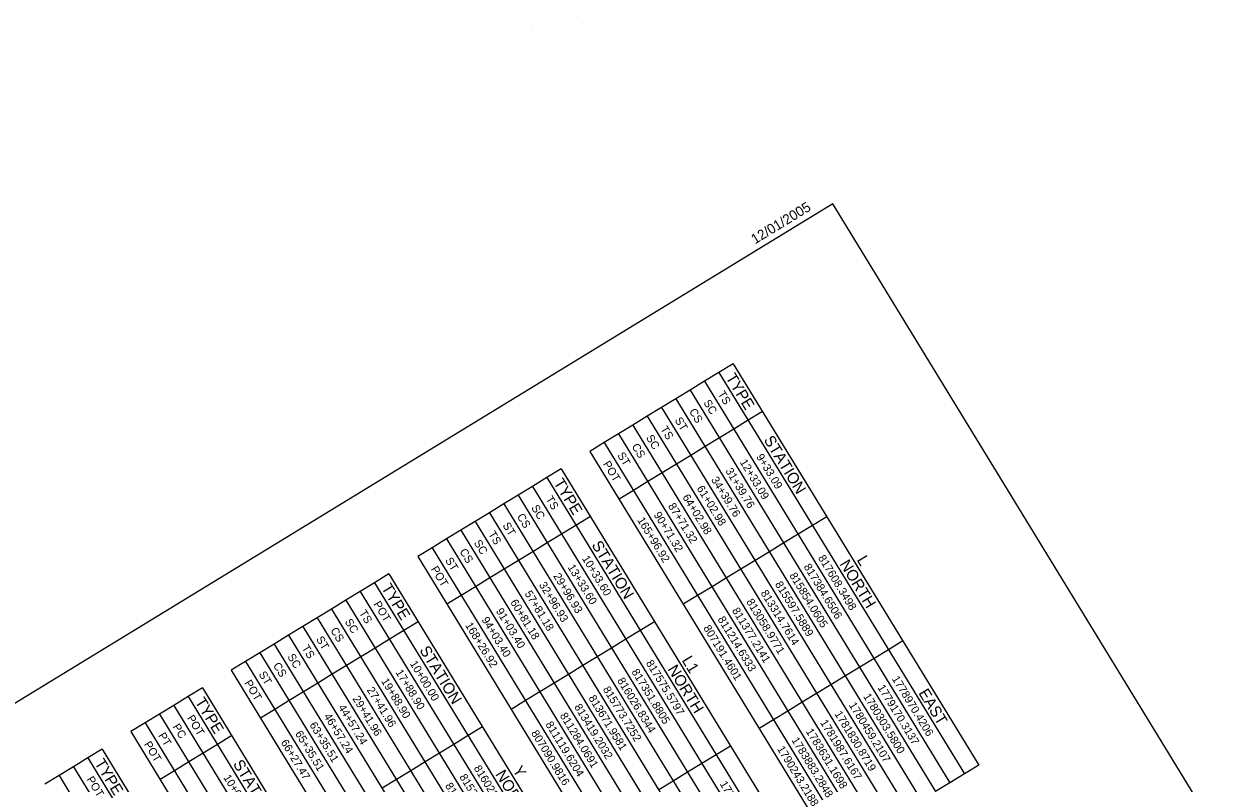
# Model space of a CAD drawing. Extents: x 1753086 to 1770987, y 792577 to 812636.
# Drawn here: x 1758064 to 1764623, y 808460 to 812636 of the extents above; entities that cross this region are included whole.
import ezdxf

# ---------------------------------------------------------------- set-up
doc = ezdxf.new("R2010")
doc.units = 0
for name, color, linetype in [('CTL Sheet Border CELL', 7, 'Continuous'), ('CTL Sheet Notes CELL', 7, 'Continuous'), ('CTL Sheet Table Cell', 7, 'Continuous'), ('CTL Sheet Text', 7, 'Continuous'), ('Sheet Data Field CELL', 7, 'Continuous')]:
    doc.layers.add(name, color=color, linetype=linetype)

msp = doc.modelspace()

# ---------------------------------------------------------------- linework, layer by layer
at = {"layer": 'CTL Sheet Border CELL'}
msp.add_lwpolyline([(1770671.7, 798289.4), (1762511, 811645.8), (1753161.6, 805933.4), (1761322.3, 792577)], close=True, dxfattribs=at)
at = {"layer": 'CTL Sheet Table Cell'}
for p, q in [((1761963.3, 810766.2), (1761884.4, 810718)), ((1761963.3, 810766.2), (1763312.2, 808558.5)), ((1761884.4, 810718), (1761805.6, 810669.9)), ((1761884.4, 810718), (1763233.3, 808510.3)), ((1761726.7, 810621.7), (1761647.9, 810573.5)), ((1761805.6, 810669.9), (1761726.7, 810621.7)), ((1761726.7, 810621.7), (1763075.6, 808414)), ((1761805.6, 810669.9), (1763154.5, 808462.2)), ((1761647.9, 810573.5), (1761569, 810525.3)), ((1761647.9, 810573.5), (1762996.8, 808365.8)), ((1761490.2, 810477.2), (1761411.3, 810429)), ((1761569, 810525.3), (1761490.2, 810477.2)), ((1761490.2, 810477.2), (1762839.1, 808269.4)), ((1761569, 810525.3), (1762917.9, 808317.6)), ((1762123.8, 810503.4), (1762045, 810455.2)), ((1761411.3, 810429), (1761332.5, 810380.8)), ((1761411.3, 810429), (1762760.2, 808221.3)), ((1762045, 810455.2), (1761966.1, 810407)), ((1761332.5, 810380.8), (1761253.6, 810332.6)), ((1761332.5, 810380.8), (1762681.4, 808173.1)), ((1761887.3, 810358.9), (1761808.5, 810310.7)), ((1761966.1, 810407), (1761887.3, 810358.9)), ((1761253.6, 810332.6), (1761174.8, 810284.5)), ((1761174.8, 810284.5), (1762523.7, 808076.7)), ((1761253.6, 810332.6), (1762602.5, 808124.9)), ((1761808.5, 810310.7), (1761729.6, 810262.5)), ((1761650.8, 810214.3), (1761571.9, 810166.2)), ((1761729.6, 810262.5), (1761650.8, 810214.3)), ((1761017.1, 810188.1), (1760938.2, 810139.9)), ((1761017.1, 810188.1), (1762366, 807980.4)), ((1761571.9, 810166.2), (1761493.1, 810118)), ((1760859.4, 810091.8), (1760780.5, 810043.6)), ((1760938.2, 810139.9), (1760859.4, 810091.8)), ((1760859.4, 810091.8), (1762208.3, 807884)), ((1760938.2, 810139.9), (1762287.2, 807932.2)), ((1761493.1, 810118), (1761414.2, 810069.8)), ((1760780.5, 810043.6), (1760701.7, 809995.4)), ((1760780.5, 810043.6), (1762129.5, 807835.9)), ((1761414.2, 810069.8), (1761335.4, 810021.6)), ((1760701.7, 809995.4), (1760622.9, 809947.2)), ((1760701.7, 809995.4), (1762050.6, 807787.7)), ((1760544, 809899.1), (1760465.2, 809850.9)), ((1760622.9, 809947.2), (1760544, 809899.1)), ((1760544, 809899.1), (1761892.9, 807691.3)), ((1760622.9, 809947.2), (1761971.8, 807739.5)), ((1761177.7, 809925.3), (1761098.8, 809877.1)), ((1762477.1, 809925.2), (1762398.3, 809877)), ((1760465.2, 809850.9), (1760386.3, 809802.7)), ((1760465.2, 809850.9), (1761814.1, 807643.2)), ((1761020, 809828.9), (1760941.1, 809780.8)), ((1761098.8, 809877.1), (1761020, 809828.9)), ((1762319.4, 809828.8), (1762240.6, 809780.7)), ((1762398.3, 809877), (1762319.4, 809828.8)), ((1760307.5, 809754.5), (1760228.6, 809706.4)), ((1760386.3, 809802.7), (1760307.5, 809754.5)), ((1760307.5, 809754.5), (1761656.4, 807546.8)), ((1760386.3, 809802.7), (1761735.2, 807595)), ((1760941.1, 809780.8), (1760862.3, 809732.6)), ((1762240.6, 809780.7), (1762161.7, 809732.5)), ((1760228.6, 809706.4), (1761577.5, 807498.6)), ((1760862.3, 809732.6), (1760783.4, 809684.4)), ((1762161.7, 809732.5), (1762082.9, 809684.3)), ((1760704.6, 809636.2), (1760625.7, 809588.1)), ((1760783.4, 809684.4), (1760704.6, 809636.2)), ((1762004, 809636.1), (1761925.2, 809588)), ((1762082.9, 809684.3), (1762004, 809636.1)), ((1759992.1, 809561.8), (1759913.2, 809513.7)), ((1760070.9, 809610), (1759992.1, 809561.8)), ((1759992.1, 809561.8), (1761341, 807354.1)), ((1760070.9, 809610), (1761419.8, 807402.3)), ((1760625.7, 809588.1), (1760546.9, 809539.9)), ((1761925.2, 809588), (1761846.4, 809539.8)), ((1759913.2, 809513.7), (1759834.4, 809465.5)), ((1759913.2, 809513.7), (1761262.1, 807305.9)), ((1760468.1, 809491.7), (1760389.2, 809443.5)), ((1760546.9, 809539.9), (1760468.1, 809491.7)), ((1761846.4, 809539.8), (1761767.5, 809491.6)), ((1759834.4, 809465.5), (1759755.5, 809417.3)), ((1759834.4, 809465.5), (1761183.3, 807257.8)), ((1761767.5, 809491.6), (1761688.7, 809443.4)), ((1759676.7, 809369.1), (1759597.8, 809321)), ((1759755.5, 809417.3), (1759676.7, 809369.1)), ((1759676.7, 809369.1), (1761025.6, 807161.4)), ((1759755.5, 809417.3), (1761104.5, 807209.6)), ((1759597.8, 809321), (1759519, 809272.8)), ((1759597.8, 809321), (1760946.8, 807113.2)), ((1760152.7, 809299), (1760073.8, 809250.8)), ((1760231.5, 809347.2), (1760152.7, 809299)), ((1761452.1, 809298.9), (1761373.3, 809250.7)), ((1761531, 809347.1), (1761452.1, 809298.9)), ((1759519, 809272.8), (1759440.1, 809224.6)), ((1759519, 809272.8), (1760867.9, 807065.1)), ((1760073.8, 809250.8), (1759995, 809202.7)), ((1761373.3, 809250.7), (1761294.4, 809202.6)), ((1762894.7, 809241.8), (1762815.8, 809193.7)), ((1759361.3, 809176.4), (1759282.5, 809128.3)), ((1759440.1, 809224.6), (1759361.3, 809176.4)), ((1759361.3, 809176.4), (1760710.2, 806968.7)), ((1759440.1, 809224.6), (1760789.1, 807016.9)), ((1759995, 809202.7), (1759916.1, 809154.5)), ((1761294.4, 809202.6), (1761215.6, 809154.4)), ((1762815.8, 809193.7), (1762737, 809145.5)), ((1759282.5, 809128.3), (1759203.6, 809080.1)), ((1759282.5, 809128.3), (1760631.4, 806920.5)), ((1759837.3, 809106.3), (1759758.4, 809058.1)), ((1759916.1, 809154.5), (1759837.3, 809106.3)), ((1761136.7, 809106.2), (1761057.9, 809058)), ((1761215.6, 809154.4), (1761136.7, 809106.2)), ((1762737, 809145.5), (1762658.1, 809097.3)), ((1759203.6, 809080.1), (1760552.5, 806872.4)), ((1759758.4, 809058.1), (1759679.6, 809010)), ((1761057.9, 809058), (1760979, 809009.8)), ((1762579.3, 809049.1), (1762500.4, 809001)), ((1762658.1, 809097.3), (1762579.3, 809049.1)), ((1759045.9, 808983.7), (1758967.1, 808935.5)), ((1759045.9, 808983.7), (1760394.8, 806776)), ((1759679.6, 809010), (1759600.7, 808961.8)), ((1760979, 809009.8), (1760900.2, 808961.7)), ((1762500.4, 809001), (1762421.6, 808952.8)), ((1758967.1, 808935.5), (1758888.2, 808887.4)), ((1758967.1, 808935.5), (1760316, 806727.8)), ((1759521.9, 808913.6), (1759443, 808865.4)), ((1759600.7, 808961.8), (1759521.9, 808913.6)), ((1760821.3, 808913.5), (1760742.5, 808865.3)), ((1760900.2, 808961.7), (1760821.3, 808913.5)), ((1762342.7, 808904.6), (1762263.9, 808856.4)), ((1762421.6, 808952.8), (1762342.7, 808904.6)), ((1758809.4, 808839.2), (1758730.5, 808791)), ((1758888.2, 808887.4), (1758809.4, 808839.2)), ((1758809.4, 808839.2), (1760158.3, 806631.5)), ((1758888.2, 808887.4), (1760237.1, 806679.7)), ((1759443, 808865.4), (1759364.2, 808817.3)), ((1762263.9, 808856.4), (1762185, 808808.3)), ((1758730.5, 808791), (1758651.7, 808742.8)), ((1758730.5, 808791), (1760079.4, 806583.3)), ((1762185, 808808.3), (1762106.2, 808760.1)), ((1758651.7, 808742.8), (1760000.6, 806535.1)), ((1759206.5, 808720.9), (1759127.7, 808672.7)), ((1760506, 808720.8), (1760427.1, 808672.6)), ((1760584.8, 808769), (1760506, 808720.8)), ((1758494, 808646.5), (1758415.1, 808598.3)), ((1758494, 808646.5), (1759842.9, 806438.8)), ((1759127.7, 808672.7), (1759048.8, 808624.5)), ((1760427.1, 808672.6), (1760348.3, 808624.4)), ((1761948.5, 808663.7), (1761869.6, 808615.6)), ((1758415.1, 808598.3), (1758336.3, 808550.1)), ((1758415.1, 808598.3), (1759764.1, 806390.6)), ((1758970, 808576.4), (1758891.1, 808528.2)), ((1759048.8, 808624.5), (1758970, 808576.4)), ((1760269.4, 808576.3), (1760190.6, 808528.1)), ((1760348.3, 808624.4), (1760269.4, 808576.3)), ((1761869.6, 808615.6), (1761790.8, 808567.4)), ((1758336.3, 808550.1), (1758257.4, 808502)), ((1758336.3, 808550.1), (1759685.2, 806342.4)), ((1758891.1, 808528.2), (1758812.3, 808480)), ((1760190.6, 808528.1), (1760111.7, 808479.9)), ((1761711.9, 808519.2), (1761633.1, 808471)), ((1761790.8, 808567.4), (1761711.9, 808519.2)), ((1763233.3, 808510.3), (1763154.5, 808462.2)), ((1763312.2, 808558.5), (1763233.3, 808510.3)), ((1758257.4, 808502), (1758178.6, 808453.8)), ((1758257.4, 808502), (1759606.4, 806294.2)), ((1760111.7, 808479.9), (1760032.9, 808431.7)), ((1761633.1, 808471), (1761554.2, 808422.9)), ((1763154.5, 808462.2), (1763075.6, 808414))]:
    msp.add_line(p, q, dxfattribs=at)
at = {"layer": 'Sheet Data Field CELL'}
for p, q in [((1760861.4, 812629.4), (1760861.4, 812629.4)), ((1761131.9, 812635.7), (1761131.9, 812635.7))]:
    msp.add_line(p, q, dxfattribs=at)

# ---------------------------------------------------------------- texts
at = {"layer": 'CTL Sheet Notes CELL'}
for s, p in [('TYPE', (1761919.4, 810690.3)), ('STATION', (1762128.6, 810348)), ('TYPE', (1760973.3, 810112.2)), ('STATION', (1761182.4, 809769.9)), ('NORTH', (1762545.8, 809665.1)), ('L', (1762640.2, 809687.8)), ('TYPE', (1760027.1, 809534.1)), ('STATION', (1760236.2, 809191.8)), ('NORTH', (1761599.7, 809086.9)), ('L1', (1761678.1, 809135.7)), ('EAST', (1762979.3, 808955.6)), ('TYPE', (1759002.1, 808907.8)), ('TYPE', (1758450.2, 808570.5)), ('STATION', (1759211.2, 808565.5)), ('NORTH', (1760653.5, 808508.8)), ('Y', (1760747.9, 808531.6))]:
    msp.add_text(s, height=61.6, rotation=301.42495, dxfattribs=at).set_placement(p)
at = {"layer": 'CTL Sheet Text'}
for s, p in [('TS ', (1761876.2, 810600.7)), ('SC ', (1761797.3, 810552.6)), ('CS ', (1761718.5, 810504.4)), ('TS ', (1761560.8, 810408)), ('ST ', (1761639.6, 810456.2)), ('SC ', (1761481.9, 810359.9)), ('ST ', (1761324.2, 810263.5)), ('CS ', (1761403.1, 810311.7)), ('POT', (1761245.4, 810215.3)), ('12+33.09', (1761997.3, 810225.2)), ('9+33.09', (1762087.6, 810254.7)), ('31+39.76', (1761918.5, 810177)), ('61+02.98', (1761760.8, 810080.6)), ('34+39.76', (1761839.7, 810128.8)), ('TS ', (1760930, 810022.6)), ('64+02.98', (1761682, 810032.5)), ('SC ', (1760851.1, 809974.5)), ('90+71.32', (1761524.3, 809936.1)), ('87+71.32', (1761603.1, 809984.3)), ('ST ', (1760693.5, 809878.1)), ('CS ', (1760772.3, 809926.3)), ('165+96.92', (1761434, 809906.6)), ('TS ', (1760614.6, 809829.9)), ('SC ', (1760535.8, 809781.8)), ('ST ', (1760378.1, 809685.4)), ('CS ', (1760456.9, 809733.6)), ('10+33.60', (1761130, 809695.2)), ('817608.3498', (1762427.5, 809698.5)), ('POT', (1760299.2, 809637.2)), ('13+33.60', (1761051.2, 809647.1)), ('817384.6506', (1762348.6, 809650.3)), ('32+96.93', (1760893.5, 809550.7)), ('29+96.93', (1760972.3, 809598.9)), ('815597.5889', (1762190.9, 809553.9)), ('815854.0605', (1762269.8, 809602.1)), ('57+81.18', (1760814.6, 809502.5)), ('813314.7614', (1762112.1, 809505.7)), ('POT', (1759983.8, 809444.5)), ('60+81.18', (1760735.8, 809454.4)), ('811377.2141', (1761954.4, 809409.4)), ('813058.9771', (1762033.2, 809457.6)), ('SC ', (1759826.1, 809348.2)), ('TS ', (1759905, 809396.4)), ('94+03.40', (1760578.1, 809358)), ('91+03.40', (1760656.9, 809406.2)), ('811214.6333', (1761875.5, 809361.2)), ('CS ', (1759747.3, 809300)), ('168+26.92', (1760487.9, 809328.5)), ('807191.4601', (1761796.7, 809313)), ('ST ', (1759668.4, 809251.8)), ('SC ', (1759510.7, 809155.5)), ('TS ', (1759589.6, 809203.6)), ('CS ', (1759431.9, 809107.3)), ('10+00.00', (1760183.9, 809117.1)), ('817575.5797', (1761481.3, 809120.3)), ('ST ', (1759353, 809059.1)), ('19+88.90', (1760026.2, 809020.8)), ('17+88.90', (1760105, 809069)), ('816026.8344', (1761323.6, 809024)), ('817351.8805', (1761402.4, 809072.2)), ('1778970.4206', (1762833.6, 809033.7)), ('POT', (1759274.2, 809010.9)), ('27+41.96', (1759947.3, 808972.6)), ('815773.7252', (1761244.8, 808975.8)), ('1779170.3137', (1762754.8, 808985.6)), ('29+41.96', (1759868.5, 808924.4)), ('813671.9581', (1761165.9, 808927.6)), ('1780459.2107', (1762597.1, 808889.2)), ('1780303.5800', (1762675.9, 808937.4)), ('POT', (1758958.8, 808818.2)), ('44+57.24', (1759789.6, 808876.3)), ('811284.0691', (1761008.2, 808831.3)), ('813419.2032', (1761087.1, 808879.5)), ('1781830.8719', (1762518.2, 808841)), ('PC ', (1758880, 808770.1)), ('63+35.51', (1759631.9, 808779.9)), ('46+57.24', (1759710.8, 808828.1)), ('811119.6204', (1760929.4, 808783.1)), ('1781987.6167', (1762439.4, 808792.9)), ('PT ', (1758801.1, 808721.9)), ('65+35.51', (1759553.1, 808731.7)), ('807090.9816', (1760850.5, 808734.9)), ('1783883.2848', (1762281.7, 808696.5)), ('1783631.1698', (1762360.5, 808744.7)), ('POT', (1758722.3, 808673.7)), ('66+27.47', (1759474.2, 808683.6)), ('1790243.2188', (1762202.8, 808648.3)), ('815260.2910', (1760456.3, 808494.1)), ('816022.5450', (1760535.1, 808542.2)), ('POT', (1758406.9, 808481)), ('10+00.00', (1759158.9, 808490.9)), ('815067.8180', (1760377.4, 808445.9)), ('1779123.9794', (1761887.4, 808455.6))]:
    msp.add_text(s, height=44, rotation=301.42495, dxfattribs=at).set_placement(p)
at = {"layer": 'Sheet Data Field CELL'}
msp.add_text('12/01/2005', height=54.78, rotation=31.42495, dxfattribs=at).set_placement((1762082.3, 811422.2))

doc.saveas('drawing.dxf')
